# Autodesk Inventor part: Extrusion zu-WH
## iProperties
Shininess: 20.0
Length Units: 11269
Angle Units: 11279
Time Units: 11290
Mass Units: 11283
Length Display Precision: 3
Angle Display Precision: 2
Created: 2003-05
Part Number: Extrusion zu-WH
Material: Standard
Description: Artikel
Document SubType Name: Modellieren
Designer: Seiler U.
Cost Center: 0,061 kg
Authority: 60859,8 mm^3
Density: 0.0
Volumn: 0.0
Area: 0.0
PropertySet Name: Model Information
Control State: 0
Master: False
Checked Out: False
SaveDate: 2003-05-13
SaveTime: 20:45
TotalMass: 0,061 kg
TotalVolume: 60859,8 mm^3
Title: Werkstoff
Subject: Werkstoff-Nr.
Author: Seiler U.
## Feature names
1. Extrusion1
2. Extrusion2
3. Höhe eingegeben Extrusion3 [Extrusion]
4. Extrusion4
5. Extrusion5
